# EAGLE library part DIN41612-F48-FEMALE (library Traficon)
Female Eurocard connector PCB-mounting straight
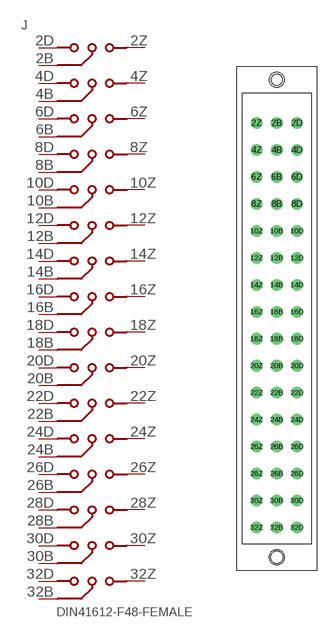
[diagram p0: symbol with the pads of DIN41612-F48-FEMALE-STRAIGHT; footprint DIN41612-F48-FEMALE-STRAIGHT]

Designator prefix J

## DIN41612-F48-FEMALE  [DIN41612-F48-FEMALE-STRAIGHT]
2B  2B
2D  2D
2Z  2Z
4B  4B
4D  4D
4Z  4Z
6B  6B
6D  6D
6Z  6Z
8B  8B
8D  8D
8Z  8Z
10B  10B
10D  10D
10Z  10Z
12B  12B
12D  12D
12Z  12Z
14B  14B
14D  14D
14Z  14Z
16B  16B
16D  16D
16Z  16Z
18B  18B
18D  18D
18Z  18Z
20B  20B
20D  20D
20Z  20Z
22B  22B
22D  22D
22Z  22Z
24B  24B
24D  24D
24Z  24Z
26B  26B
26D  26D
26Z  26Z
28B  28B
28D  28D
28Z  28Z
30B  30B
30D  30D
30Z  30Z
32B  32B
32D  32D
32Z  32Z

## Footprint DIN41612-F48-FEMALE-STRAIGHT (pad centres in mm)
drill 1.016 pad 2.184 round: 2B 0,36.82; 2D 3.81,36.82; 2Z -3.81,36.82; 4B 0,31.74; 4D 3.81,31.74; 4Z -3.81,31.74; 6B 0,26.66; 6D 3.81,26.66; 6Z -3.81,26.66; 8B 0,21.58; 8D 3.81,21.58; 8Z -3.81,21.58; 10B 0,16.5; 10D 3.81,16.5; 10Z -3.81,16.5; 12B 0,11.42; 12D 3.81,11.42; 12Z -3.81,11.42; 14B 0,6.34; 14D 3.81,6.34; 14Z -3.81,6.34; 16B 0,1.26; 16D 3.81,1.26; 16Z -3.81,1.26; 18B 0,-3.82; 18D 3.81,-3.82; 18Z -3.81,-3.82; 20B 0,-8.9; 20D 3.81,-8.9; 20Z -3.81,-8.9; 22B 0,-13.98; 22D 3.81,-13.98; 22Z -3.81,-13.98; 24B 0,-19.06; 24D 3.81,-19.06; 24Z -3.81,-19.06; 26B 0,-24.14; 26D 3.81,-24.14; 26Z -3.81,-24.14; 28B 0,-29.22; 28D 3.81,-29.22; 28Z -3.81,-29.22; 30B 0,-34.3; 30D 3.81,-34.3; 30Z -3.81,-34.3; 32B 0,-39.38; 32D 3.81,-39.38; 32Z -3.81,-39.38
hole 2.8 at 0,45
hole 2.8 at 0,-45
